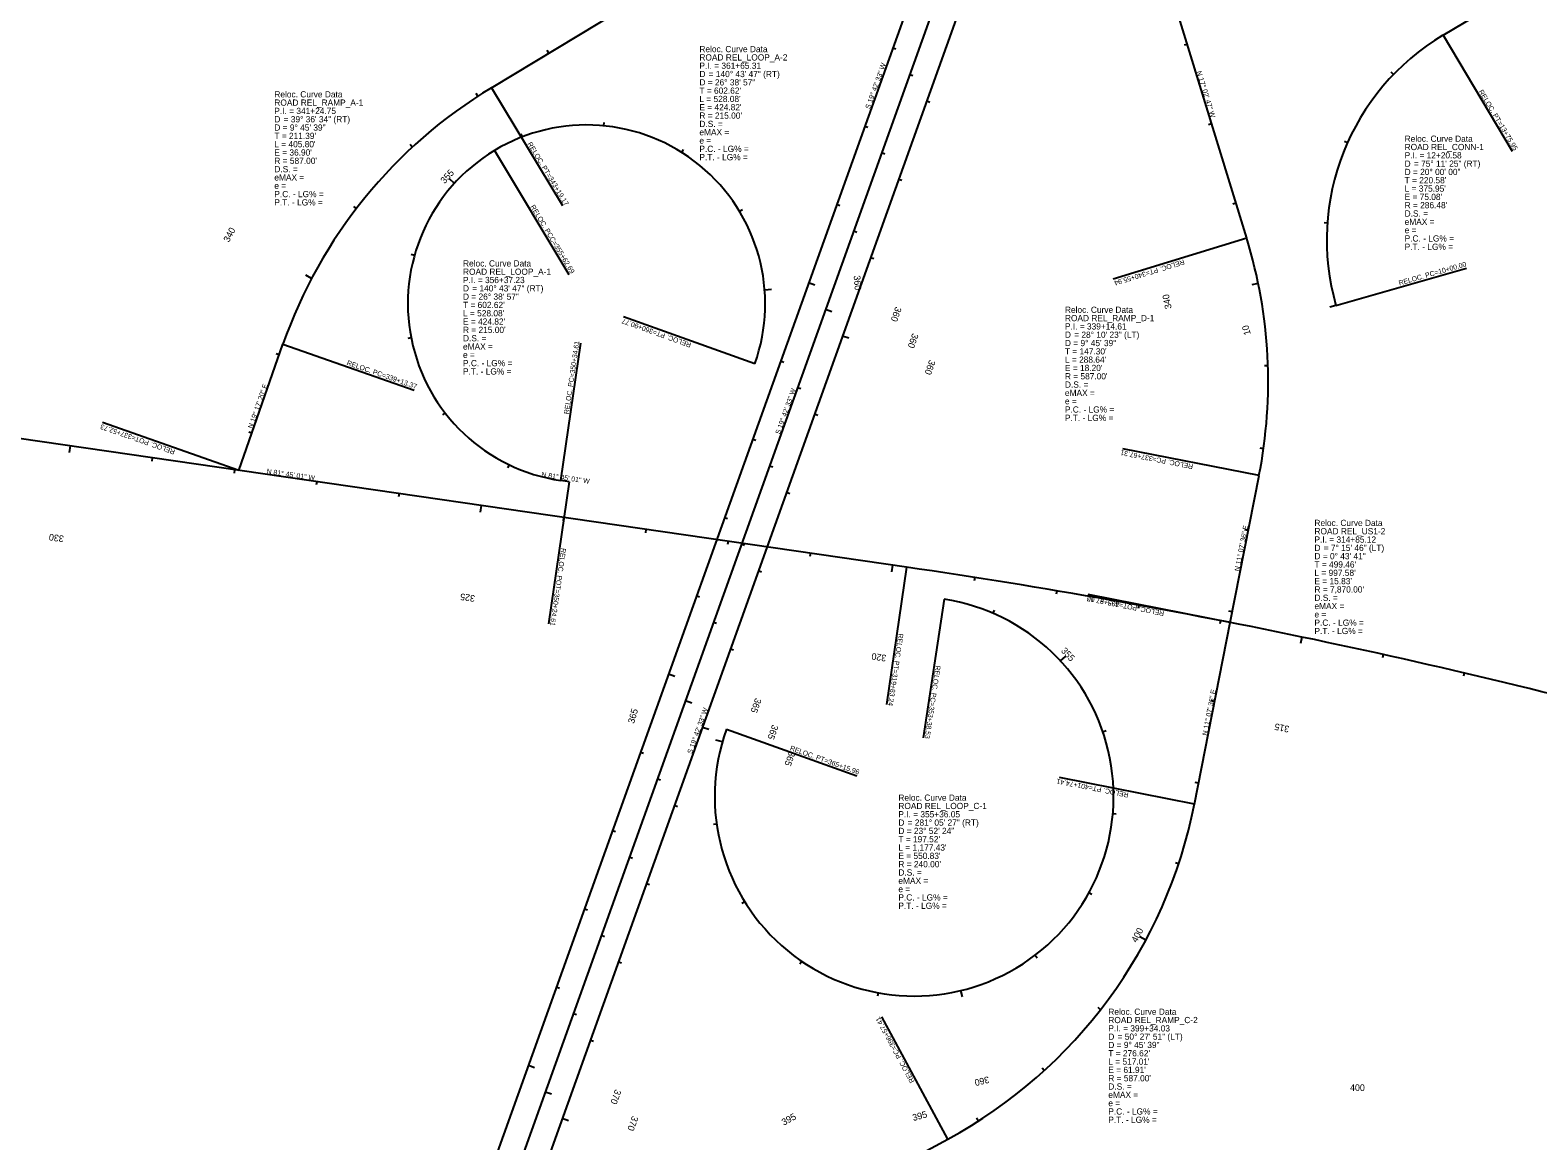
# Model space of a CAD drawing. Extents: x 1902569 to 1961902, y 757103 to 798350.
# Drawn here: x 1940075 to 1941889, y 779818 to 781155 of the extents above; entities that cross this region are included whole.
import ezdxf

# ---------------------------------------------------------------- set-up
doc = ezdxf.new("R2010")
doc.units = 0
for name, color, linetype in [('RD_HC_CL_Rel', 7, 'Continuous'), ('RD_HC_Data_Rel', 7, 'Continuous'), ('RD_HC_Data_Tic_Rel', 7, 'Continuous'), ('RD_HC_TX_Rel_Sta50', 7, 'Continuous')]:
    doc.layers.add(name, color=color, linetype=linetype)

msp = doc.modelspace()

# ---------------------------------------------------------------- linework, layer by layer
at = {"layer": 'RD_HC_CL_Rel'}
for p, q in [((1941878, 783269.7), (1940313.2, 778901.6)), ((1941633, 782497), (1940341.4, 778891.4)), ((1941661.2, 782486.8), (1940101.7, 778133.2)), ((1941774.7, 781148.4), (1942162.1, 781379.3)), ((1940629.7, 781085.3), (1941012.4, 781316.1)), ((1941538.5, 780904.1), (1941432.9, 781248.5)), ((1940325.8, 780624.9), (1940378.9, 780776.6)), ((1941129, 780508.5), (1939646.6, 780723.4)), ((1940723.3, 780611.3), (1940713.4, 780612.7)), ((1941518.5, 780442), (1941553.3, 780618.8)), ((1941475.6, 780223.6), (1941518.5, 780442)), ((1940872.9, 779655.1), (1941178.9, 779820.6))]:
    msp.add_line(p, q, dxfattribs=at)
for centre, radius, start, end in [((1941921.3, 780902.3), 286.5, 120.7968, 195.9871), ((1940933, 780582.7), 587, 121.1016, 160.7111), ((1940744.2, 780825.5), 215, 340.2909, 121.0206), ((1940744.2, 780825.5), 215, 121.0206, 261.7503), ((1940977.3, 780732), 587, 348.8732, 17.0463), ((1939999.8, 772719.9), 7870, 74.48765, 81.7503), ((1941138.4, 780232.6), 240, 160.2909, 81.3818), ((1940899.6, 780336.9), 587, 298.4092, 348.8732)]:
    msp.add_arc(centre, radius, start, end, dxfattribs=at)
at = {"layer": 'RD_HC_Data_Rel'}
for p, q in [((1941774.7, 781148.4), (1941857.8, 781008.9)), ((1940629.7, 781085.3), (1940715.2, 780943.6)), ((1940633.4, 781009.7), (1940723.1, 780860.6)), ((1941538.5, 780904.1), (1941378, 780854.9)), ((1941645.9, 780823.4), (1941802.8, 780868.3)), ((1940946.6, 780753), (1940788.8, 780809.5)), ((1940378.9, 780776.6), (1940536.8, 780721.3)), ((1940713.4, 780612.7), (1940737.4, 780778.1)), ((1940325.8, 780624.9), (1940161.8, 780682.4)), ((1941553.3, 780618.8), (1941389.3, 780651)), ((1940723.3, 780611.3), (1940698.5, 780440.5)), ((1941129, 780508.5), (1941105.1, 780343.4)), ((1941174.4, 780469.9), (1941149.1, 780303.4)), ((1941518.5, 780442), (1941347.9, 780475.6)), ((1941518.5, 780442), (1941349.1, 780475.3)), ((1940912.5, 780313.6), (1941069.5, 780257.3)), ((1941475.6, 780223.6), (1941313.4, 780255.5)), ((1941178.9, 779820.6), (1941099.4, 779967.6))]:
    msp.add_line(p, q, dxfattribs=at)
at = {"layer": 'RD_HC_Data_Tic_Rel'}
for p, q in [((1941467, 781137.4), (1941463.2, 781136.3)), ((1940698.9, 781127), (1940696.9, 781130.5)), ((1941112.6, 781133.2), (1941116.4, 781131.9)), ((1941133, 781101.3), (1941136.8, 781099.9)), ((1941715.3, 781101.3), (1941712.4, 781104.1)), ((1940613.5, 781075.1), (1940611.3, 781078.5)), ((1941153.5, 781069.3), (1941157.2, 781068)), ((1940666.9, 781026.1), (1940665.5, 781029.8)), ((1940765.1, 781039.5), (1940765.5, 781043.4)), ((1941078.9, 781039.1), (1941082.7, 781037.8)), ((1941496.3, 781041.8), (1941492.5, 781040.7)), ((1940534.6, 781013.8), (1940531.9, 781016.8)), ((1940858.9, 781007.4), (1940861, 781010.8)), ((1941659.7, 781018.9), (1941656, 781020.5)), ((1941099.3, 781007.2), (1941103.1, 781005.8)), ((1940585.2, 780970.1), (1940579.2, 780975.5)), ((1941119.7, 780975.2), (1941123.5, 780973.9)), ((1940467.3, 780940.1), (1940464.1, 780942.5)), ((1940928.3, 780936.6), (1940931.7, 780938.7)), ((1941045.2, 780945), (1941048.9, 780943.6)), ((1941525.6, 780946.2), (1941521.8, 780945.1)), ((1941635.6, 780922.3), (1941631.6, 780922.6)), ((1941065.6, 780913), (1941069.3, 780911.7)), ((1940537.2, 780883.4), (1940533.3, 780884.5)), ((1941086, 780881.1), (1941089.8, 780879.7)), ((1940413.4, 780855.9), (1940406.4, 780859.7)), ((1941011.4, 780850.8), (1941019, 780848.1)), ((1941552.4, 780849.9), (1941544.5, 780848.3)), ((1940958.6, 780842.3), (1940966.6, 780842.9)), ((1941031.9, 780818.9), (1941039.4, 780816.2)), ((1941645.9, 780823.4), (1941638.3, 780821.2)), ((1940533.2, 780784.4), (1940529.3, 780783.6)), ((1941052.3, 780786.9), (1941059.8, 780784.2)), ((1940374.5, 780763.9), (1940370.7, 780765.3)), ((1940977.7, 780756.7), (1940981.5, 780755.3)), ((1941564, 780750.7), (1941560, 780750.6)), ((1940998.1, 780724.7), (1941001.9, 780723.4)), ((1940574.1, 780694.1), (1940570.9, 780691.6)), ((1941018.6, 780692.8), (1941022.3, 780691.4)), ((1940341.5, 780669.6), (1940337.7, 780670.9)), ((1940122.8, 780654.4), (1940121.6, 780646.5)), ((1940944, 780662.5), (1940947.8, 780661.2)), ((1941558.7, 780651), (1941554.7, 780651.5)), ((1940221.7, 780640), (1940221.2, 780636.1)), ((1940651.1, 780631.7), (1940649.3, 780628.1)), ((1940964.4, 780630.6), (1940968.2, 780629.2)), ((1940320.7, 780625.7), (1940320.1, 780621.7)), ((1940419.7, 780611.3), (1940419.1, 780607.4)), ((1940518.6, 780597), (1940518.1, 780593)), ((1940984.8, 780598.6), (1940988.6, 780597.3)), ((1940617.6, 780582.6), (1940616.4, 780574.7)), ((1940716.6, 780568.3), (1940716, 780564.3)), ((1940910.3, 780568.4), (1940914, 780567)), ((1940815.5, 780553.9), (1940815, 780550)), ((1940914.5, 780539.6), (1940913.9, 780535.6)), ((1941540.3, 780552.7), (1941536.4, 780553.5)), ((1940930.7, 780536.4), (1940934.4, 780535.1)), ((1941013.5, 780525.2), (1941012.9, 780521.3)), ((1940951.1, 780504.5), (1940954.9, 780503.1)), ((1941112.4, 780510.9), (1941111.3, 780503)), ((1941211.3, 780496.1), (1941210.7, 780492.2)), ((1940876.5, 780474.3), (1940880.3, 780472.9)), ((1941310, 780480.1), (1941309.4, 780476.1)), ((1941233.3, 780453.1), (1941234.9, 780456.7)), ((1941408.5, 780462.8), (1941407.8, 780458.9)), ((1941521, 780454.6), (1941517.1, 780455.4)), ((1940897, 780442.3), (1940900.7, 780441)), ((1941506.8, 780444.3), (1941506, 780440.4)), ((1940917.4, 780410.4), (1940921.1, 780409)), ((1941604.8, 780424.5), (1941603.2, 780416.7)), ((1941314.4, 780395.8), (1941320.3, 780401.2)), ((1941702.6, 780403.5), (1941701.7, 780399.6)), ((1940842.8, 780380.1), (1940850.3, 780377.4)), ((1941800.1, 780381.2), (1941799.2, 780377.4)), ((1940863.2, 780348.2), (1940870.8, 780345.5)), ((1941499.8, 780346.8), (1941495.9, 780347.6)), ((1940883.7, 780316.2), (1940891.2, 780313.5)), ((1941365.4, 780310.6), (1941369.2, 780311.9)), ((1940809.1, 780286), (1940812.9, 780284.6)), ((1940907.6, 780298.4), (1940899.9, 780300.6)), ((1940829.5, 780254), (1940833.3, 780252.7)), ((1941480.5, 780248.7), (1941476.6, 780249.5)), ((1940849.9, 780222.1), (1940853.7, 780220.7)), ((1941377.5, 780212.1), (1941381.5, 780211.7)), ((1940900.7, 780199.3), (1940896.8, 780198.8)), ((1940775.4, 780191.8), (1940779.1, 780190.5)), ((1940795.8, 780159.9), (1940799.6, 780158.5)), ((1941456.6, 780151.7), (1941452.8, 780152.9)), ((1940816.2, 780127.9), (1940820, 780126.6)), ((1940934.5, 780106), (1940931.1, 780103.9)), ((1941348.7, 780117.1), (1941352.2, 780115.1)), ((1940741.6, 780097.7), (1940745.4, 780096.3)), ((1940762.1, 780065.7), (1940765.8, 780064.4)), ((1941417.2, 780059.9), (1941410.1, 780063.7)), ((1940782.5, 780033.8), (1940786.2, 780032.4)), ((1941003.2, 780034.3), (1941001, 780031)), ((1941284, 780041.8), (1941286.4, 780038.6)), ((1940707.9, 780003.5), (1940711.7, 780002.2)), ((1941095, 779996.6), (1941094.3, 779992.6)), ((1941194.3, 779999.2), (1941196.2, 779991.5)), ((1941362.7, 779976.2), (1941359.6, 779978.7)), ((1940728.3, 779971.6), (1940732.1, 779970.2)), ((1940748.8, 779939.6), (1940752.5, 779938.3)), ((1940674.2, 779909.4), (1940681.7, 779906.7)), ((1941294.9, 779902.9), (1941292.2, 779905.9)), ((1940694.6, 779877.5), (1940702.1, 779874.8)), ((1940715, 779845.5), (1940722.6, 779842.8)), ((1941215.6, 779842.2), (1941213.4, 779845.5))]:
    msp.add_line(p, q, dxfattribs=at)

# ---------------------------------------------------------------- texts
at = {"layer": 'RD_HC_Data_Rel'}
for s, p in [('Reloc. Curve Data', (1940880, 781128)), ('ROAD REL_LOOP_A-2', (1940880, 781118)), ('P.I. = 361+65.31', (1940880, 781108)), ('D', (1940880, 781098)), ('    = 140° 43\' 47" (RT)', (1940880, 781098)), ('Reloc. Curve Data', (1940368.6, 781073.6)), ("T = 602.62'", (1940880, 781078)), ('D = 26° 38\' 57"', (1940880, 781088)), ('ROAD REL_RAMP_A-1', (1940368.6, 781063.6)), ("L = 528.08'", (1940880, 781068)), ("E = 424.82'", (1940880, 781058)), ('P.I. = 341+24.75', (1940368.6, 781053.6)), ('D', (1940368.6, 781043.6)), ('    = 39° 36\' 34" (RT)', (1940368.6, 781043.6)), ("R = 215.00'", (1940880, 781048)), ('D.S. =', (1940880, 781038)), ("T = 211.39'", (1940368.6, 781023.6)), ('D = 9° 45\' 39"', (1940368.6, 781033.6)), ('eMAX = ', (1940880, 781028)), ('Reloc. Curve Data', (1941728.5, 781020.2)), ("L = 405.80'", (1940368.6, 781013.6)), ("E = 36.90'", (1940368.6, 781003.6)), ('e = ', (1940880, 781018)), ('P.C. - LG% = ', (1940880, 781008)), ('ROAD REL_CONN-1', (1941728.5, 781010.2)), ("R = 587.00'", (1940368.6, 780993.6)), ('D.S. =', (1940368.6, 780983.6)), ('P.T. - LG% = ', (1940880, 780998)), ('P.I. = 12+20.58', (1941728.5, 781000.2)), ('D', (1941728.5, 780990.2)), ('    = 75° 11\' 25" (RT)', (1941728.5, 780990.2)), ('eMAX = ', (1940368.6, 780973.6)), ("T = 220.58'", (1941728.5, 780970.2)), ('D = 20° 00\' 00"', (1941728.5, 780980.2)), ('e = ', (1940368.6, 780963.6)), ('P.C. - LG% = ', (1940368.6, 780953.6)), ("L = 375.95'", (1941728.5, 780960.2)), ("E = 75.08'", (1941728.5, 780950.2)), ('P.T. - LG% = ', (1940368.6, 780943.6)), ("R = 286.48'", (1941728.5, 780940.2)), ('D.S. =', (1941728.5, 780930.2)), ('eMAX = ', (1941728.5, 780920.2)), ('e = ', (1941728.5, 780910.2)), ('P.C. - LG% = ', (1941728.5, 780900.2)), ('P.T. - LG% = ', (1941728.5, 780890.2)), ('Reloc. Curve Data', (1940595.6, 780870.2)), ('ROAD REL_LOOP_A-1', (1940595.6, 780860.2)), ('P.I. = 356+37.23', (1940595.6, 780850.2)), ('D', (1940595.6, 780840.2)), ('    = 140° 43\' 47" (RT)', (1940595.6, 780840.2)), ("T = 602.62'", (1940595.6, 780820.2)), ('D = 26° 38\' 57"', (1940595.6, 780830.2)), ("L = 528.08'", (1940595.6, 780810.2)), ('Reloc. Curve Data', (1941319.8, 780814.4)), ('ROAD REL_RAMP_D-1', (1941319.8, 780804.4)), ("E = 424.82'", (1940595.6, 780800.2)), ("R = 215.00'", (1940595.6, 780790.2)), ('P.I. = 339+14.61', (1941319.8, 780794.4)), ('D', (1941319.8, 780784.4)), ('    = 28° 10\' 23" (LT)', (1941319.8, 780784.4)), ('eMAX = ', (1940595.6, 780770.2)), ('D.S. =', (1940595.6, 780780.2)), ('D = 9° 45\' 39"', (1941319.8, 780774.4)), ('e = ', (1940595.6, 780760.2)), ('P.C. - LG% = ', (1940595.6, 780750.2)), ("T = 147.30'", (1941319.8, 780764.4)), ("L = 288.64'", (1941319.8, 780754.4)), ('P.T. - LG% = ', (1940595.6, 780740.2)), ("E = 18.20'", (1941319.8, 780744.4)), ("R = 587.00'", (1941319.8, 780734.4)), ('eMAX = ', (1941319.8, 780714.4)), ('D.S. =', (1941319.8, 780724.4)), ('e = ', (1941319.8, 780704.4)), ('P.C. - LG% = ', (1941319.8, 780694.4)), ('P.T. - LG% = ', (1941319.8, 780684.4)), ('Reloc. Curve Data', (1941620, 780558)), ('ROAD REL_US1-2', (1941620, 780548)), ('P.I. = 314+85.12', (1941620, 780538)), ('D', (1941620, 780528)), ('D = 0° 43\' 41"', (1941620, 780518)), ('    = 7° 15\' 46" (LT)', (1941620, 780528)), ("T = 499.46'", (1941620, 780508)), ("L = 997.58'", (1941620, 780498)), ("E = 15.83'", (1941620, 780488)), ("R = 7,870.00'", (1941620, 780478)), ('eMAX = ', (1941620, 780458)), ('D.S. =', (1941620, 780468)), ('e = ', (1941620, 780448)), ('P.C. - LG% = ', (1941620, 780438)), ('P.T. - LG% = ', (1941620, 780428)), ('Reloc. Curve Data', (1941119.4, 780227.5)), ('ROAD REL_LOOP_C-1', (1941119.4, 780217.5)), ('P.I. = 355+36.05', (1941119.4, 780207.5)), ('D', (1941119.4, 780197.5)), ('D = 23° 52\' 24"', (1941119.4, 780187.5)), ('    = 281° 05\' 27" (RT)', (1941119.4, 780197.5)), ("T = 197.52'", (1941119.4, 780177.5)), ("L = 1,177.43'", (1941119.4, 780167.5)), ("E = 550.83'", (1941119.4, 780157.5)), ("R = 240.00'", (1941119.4, 780147.5)), ('D.S. =', (1941119.4, 780137.5)), ('eMAX = ', (1941119.4, 780127.5)), ('e = ', (1941119.4, 780117.5)), ('P.C. - LG% = ', (1941119.4, 780107.5)), ('P.T. - LG% = ', (1941119.4, 780097.5)), ('Reloc. Curve Data', (1941372, 779970)), ('ROAD REL_RAMP_C-2', (1941372, 779960)), ('P.I. = 399+34.03', (1941372, 779950)), ('D', (1941372, 779940)), ('    = 50° 27\' 51" (LT)', (1941372, 779940)), ("T = 276.62'", (1941372, 779920)), ('D = 9° 45\' 39"', (1941372, 779930)), ("L = 517.01'", (1941372, 779910)), ("E = 61.91'", (1941372, 779900)), ("R = 587.00'", (1941372, 779890)), ('D.S. =', (1941372, 779880)), ('eMAX = ', (1941372, 779870)), ('e = ', (1941372, 779860)), ('P.C. - LG% = ', (1941372, 779850)), ('P.T. - LG% = ', (1941372, 779840))]:
    msp.add_text(s, height=7.5, dxfattribs=at).set_placement(p)
for s, rotation, p in [('S 19° 42\' 33" W', 70.2909, (1941085, 781059.2)), ('N 17° 02\' 47" W', 287.0463, (1941478.1, 781104.5)), ('RELOC. PT=13+75.95', 300.7968, (1941817.3, 781080.7)), ('RELOC. PT=343+19.17', 301.1016, (1940672.8, 781017.8)), ('RELOC. PCC=355+62.69', 301.0206, (1940676.4, 780942.2)), ('RELOC. PT=340+55.94', 197.0463, (1941462.6, 780878.7)), ('RELOC. PC=10+00.00', 15.9871, (1941722.3, 780847.3)), ('RELOC. PT=360+90.77', 160.2909, (1940870.7, 780778.1)), ('RELOC. PC=350+34.61', 81.7503, (1940722.9, 780692.2)), ('RELOC. PC=339+13.37', 340.7111, (1940455.1, 780752)), ('N 19° 17\' 20" E', 70.7111, (1940342.2, 780674.8)), ('S 19° 42\' 33" W', 70.2909, (1940976.7, 780667.7)), ('RELOC. POT=337+52.73', 160.7111, (1940249.7, 780649.5)), ('RELOC. PC=337+67.31', 168.8732, (1941474.4, 780632.2)), ('N 81° 45\' 01" W', 351.7503, (1940359, 780621.1)), ('N 81° 45\' 01" W', 351.7503, (1940689.6, 780617.2)), ('N 11° 07\' 36" E', 78.8732, (1941529.5, 780503.2)), ('RELOC. POT=350+24.61', 261.7503, (1940713.8, 780531.8)), ('RELOC. POT=335+87.17', 168.8732, (1941439.6, 780455.5)), ('RELOC. POT=403+97.00', 168.8732, (1941439.6, 780455.5)), ('RELOC. PT=319+83.24', 261.7503, (1941119.5, 780429)), ('RELOC. PC=353+38.53', 261.3818, (1941164.3, 780390.5)), ('N 11° 07\' 36" E', 78.8732, (1941490.7, 780305.6)), ('S 19° 42\' 33" W', 70.2909, (1940870.9, 780283.5)), ('RELOC. PT=365+15.96', 340.2909, (1940988.4, 780288.5)), ('RELOC. PT=401+74.41', 168.8732, (1941396.7, 780237.1)), ('RELOC. PC=396+57.41', 118.4092, (1941139.1, 779890))]:
    msp.add_text(s, height=6, rotation=rotation, dxfattribs=at).set_placement(p)
at = {"layer": 'RD_HC_TX_Rel_Sta50'}
for s, rotation, p in [('355', 47.7265, (1940573.5, 780969.2)), ('340', 62.2549, (1940313.9, 780898.7)), ('360', 274.4805, (1941065.6, 780859.2)), ('340', 101.5857, (1941448.3, 780819.9)), ('360', 250.2909, (1941116, 780822.4)), ('10', 105.9871, (1941543.5, 780788.9)), ('360', 250.2909, (1941136.4, 780790.5)), ('360', 250.2909, (1941156.8, 780758.5)), ('330', 171.7503, (1940115.7, 780546.3)), ('325', 171.7503, (1940610.5, 780474.5)), ('355', 312.8334, (1941314.5, 780407.5)), ('320', 171.7503, (1941105.4, 780402.8)), ('365', 74.101, (1940801.4, 780319.8)), ('365', 250.2909, (1940947.4, 780351.7)), ('315', 168.2322, (1941590.4, 780317.2)), ('365', 250.2909, (1940967.8, 780319.7)), ('365', 250.2909, (1940988.2, 780287.8)), ('400', 61.849, (1941406.1, 780056.2)), ('360', 193.4672, (1941227.7, 779896.2)), ('400', 0.1092, (1941662.8, 779878.4)), ('370', 250.2909, (1940778.7, 779881)), ('370', 250.2909, (1940799.2, 779849)), ('395', 28.4092, (1940981.6, 779836.6)), ('395', 15.26, (1941137.5, 779842.2))]:
    msp.add_text(s, height=8, rotation=rotation, dxfattribs=at).set_placement(p)

doc.saveas('drawing.dxf')
